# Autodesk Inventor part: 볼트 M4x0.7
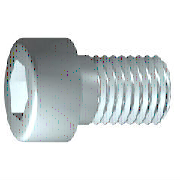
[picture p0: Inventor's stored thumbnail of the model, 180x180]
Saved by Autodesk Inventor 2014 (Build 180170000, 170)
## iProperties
IsCustomPart: 0
Created: 2015-12
Part Number: 볼트 M4x0.7
Material: 강철, 연강
Description: 6각머리 태핑 나사
Document SubType Name: Modeling
Standard: KS B 1003
Designer: mdu
Standards Organization: KS
Language: ko-KR
Size Designation: M 4 x 12
Categories: <MemberInstance><Categories><Category DisplayName="조임쇠" InternalName="e4da775c-781d-43d5-af7c-5136215cf5a6" Mnemonic="FSTN"><Category DisplayName="볼트" InternalN
Density: 7.86 g/cm^3
Appearance: 강철
Mass: 2.23465 g
Surface Area: 3.30853 cm^2
Volume: 0.284306 cm^3
Author: mdu
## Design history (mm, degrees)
sketch "스케치1"
  geometry: L1 (-1, 0)-(12, 0); L2 (12, 0)-(12, 2); L3 (12, 2)-(1.75, 2); L4 (1.75, 2)-(1.32, 2); L5 (1.32, 2)-(0, 2); L6 (0, 2)-(0, 3.5); L7 (0, 3.5)-(-4, 3.5); L8 (-4, 3.5)-(-4, 1.732); L9 (-4, 1.732)-(-2, 1.732); L10 (-2, 1.732)-(-1, 0); L11 (-7.2, 0)-(15.2, 0) reference; L12 (0, -0.7)-(0, 4.2) reference; L13 (1.75, 2)-(0, 2)
  constraints: 22 end point, 6 parallel, 2 collinear, 2 perpendicular, 1 horizontal, 1 point on line
  dimensions: "d1" = 10.25 distance from line of L3.end L2 (= GEL); "d2" = 0.42952 distance of L4.end L3.end (computed from GAL); "d3" = 4 distance between parallel lines of L8 L6 (= KOH); "d4" = 2 distance of L8.end L9.end (= INTI); "d5" = 60 deg angle of L10 L1; "d6" = 4 diameter of L3 L1 (= GD); "d7" = 4 diameter of L5 L1 (= BDM); "d8" = 3.4641 diameter of L9 L1 (= 1.1547 x SW); "d9" = 7 diameter of L7 L1 (= KOD); "d26" = 12 distance between parallel lines of L12 L2 (= NLG)
revolve "본체" sketch "스케치1" stored, may be unused: angle "d10" = 90 deg
sketch "스케치2"
  geometry: L1 (0, -4.9)-(0, 4.9) reference; L2 (-4.9, 0)-(4.9, 0) reference; L3 (1.732, 0)-(0.866, -1.5); L4 (0.866, -1.5)-(-0.866, -1.5); L5 (-0.866, -1.5)-(-1.732, 0); L6 (-1.732, 0)-(-0.866, 1.5); L7 (-0.866, 1.5)-(0.866, 1.5); L8 (0.866, 1.5)-(1.732, 0); 2 further points
  constraints: 12 end point, 1 coincident, 1 horizontal alignment, 1 point on line, 12 other
extrude "슬롯" join sketch "스케치2" stored distance "d11" = 10; taper "d12" = 0 deg
workplane "Work Plane1"
fillet "Fillet2" dims "d30" = 0.1 (= R)
body "Solid1"
fillet "모깎기1" dims "d17" = 0.4 (= RR)
feature "스레드" dims "d13" = 10.25 (= GEL), "d14" = 0
chamfer "모따기1" distance "d15" = 0.42941 (= -0.5 x SPD + 0.5 x GD); stored, may be unused: second distance "d16" = 0.42941 (= GUL), angle "d27" = 45 deg
other parameters: "GD" = 4 (= NND) [user parameter; used in 2 equation terms], "NLG" = 12 [user parameter; used in 1 equation term], "GEL" = 10.25 [user parameter; used in 2 equation terms], "KOD" = 7 [user parameter; used in 1 equation term], "KOH" = 4 [user parameter; used in 1 equation term], "INTI" = 2 [user parameter; used in 1 equation term], "GAL" = 0.42941 (= 0.61345 x PTC) [user parameter; used in 1 equation term], "GUL" = 0.42941 (= 0.61345 x PTC) [user parameter; used in 1 equation term], "BDM" = 4 (= NND) [user parameter; used in 1 equation term], "SW" = 3 [user parameter; used in 2 equation terms], "RR" = 0.4 [user parameter; used in 1 equation term], "SPD" = 3.14117 (= NND - 1.2269 x PTC) [user parameter; used in 1 equation term], "d19" = 0, "d28" = 0, "d29" = 0, "R" = 0.1 [user parameter; used in 1 equation term], "PHH" = 0.2 [user parameter], "GD1" = 3.14117 (= THREADDIA - 1.2269 x PTC) [user parameter], "THREADDIA" = 4 [user parameter; used in 1 equation term], "FAWI" = 45 deg [user parameter], "TPU" = 14.28571 (computed from PTC) [user parameter], "PTC" = 0.7 [user parameter; used in 5 equation terms], "NND" = 4 [user parameter; used in 3 equation terms], "TOA" = 30 deg [user parameter], "E0" = 3.465 (= 1.155 x SW) [user parameter]
